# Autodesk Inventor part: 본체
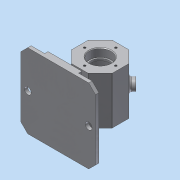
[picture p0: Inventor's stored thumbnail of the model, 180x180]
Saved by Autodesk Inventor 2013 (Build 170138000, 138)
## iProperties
Created: 2018-06
Part Number: 본체
Material: 알루미늄 6061
Document SubType Name: Modeling
Designer: Administrator
Density: 2.71 g/cm^3
Mass: 554.043 g
Surface Area: 601.93 cm^2
Volume: 204.444 cm^3
Author: Administrator
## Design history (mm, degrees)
sketch "스케치2" dims "d0" = 60
  geometry: L1 (12.426, 30)-(30, 12.426); L2 (30, 12.426)-(30, -12.426); L3 (30, -12.426)-(12.426, -30); L4 (12.426, -30)-(-12.426, -30); L5 (-12.426, -30)-(-30, -12.426); L6 (-30, -12.426)-(-30, 12.426); L7 (-30, 12.426)-(-12.426, 30); L8 (-12.426, 30)-(12.426, 30); L9 (-55, -62)-(55, -62); L10 (55, -62)-(55, -57); L11 (55, -57)-(25, -57); L12 (25, -57)-(25, -52); L13 (25, -52)-(-25, -52); L14 (-25, -52)-(-25, -57); L15 (-25, -57)-(-55, -57); L16 (-55, -57)-(-55, -62); L17 (0, 0)-(0, -62); L18 (-5, -30)-(-5, -52); L19 (5, -30)-(5, -52); 3 further points
  constraints: 38 end point, 7 parallel, 4 point on line, 3 perpendicular, 2 coincident, 2 midpoint, 2 vertical alignment, 1 collinear, 1 vertical, 21 other
  dimensions: "d4" = 62 distance of L17.start L17.end; "d5" = 10 distance between parallel lines of L9 L13; "d6" = 5 distance between parallel lines of L9 L15; "d7" = 110 distance of L9.start L9.end; "d8" = 30 distance of L14.end L15.end; "d9" = 10 distance between parallel lines of L18 L19
extrude "돌출1" new body sketch "스케치2" distance "d2" = 35; taper "d3" = 0 deg
extrude "돌출2" join sketch "스케치2" distance "d10" = 55; taper "d11" = 0 deg
extrude "돌출3" join sketch "스케치2" distance "d12" = 24; taper "d13" = 0 deg
chamfer "모따기1" distance "d14" = 10; stored, may be unused: second distance "d15" = 2, angle "d16" = 45 deg
fillet "모깎기1" dims "d17" = 5
hole "구멍1" sketch "스케치2" diameter "d18" = 28; stored, may be unused: countersink angle "d22" = 90 deg, drill point angle "d24" = 118 deg; dims "d19" = 6, "d20" = 50, "d21" = 20, "d23" = 8
hole "구멍2" diameter "d27" = 28; stored, may be unused: countersink angle "d31" = 90 deg, drill point angle "d33" = 118 deg; dims "d25" = 10, "d26" = 10, "d28" = 6, "d29" = 32, "d30" = 12, "d32" = 8
sketch "스케치3"
  geometry: C1 r 8 at (-12.426, 35); 1 further point
  constraints: 1 centre point, 1 coincident
  dimensions: "d35" = 16 diameter of C1
extrude "돌출4" join sketch "스케치3" distance "d36" = 7; taper "d37" = 0 deg
sketch "스케치4"
  geometry: L1 (24.853, 0)-(0, 0) reference; L2 (-17.574, 0)-(-17.574, 70) reference; 2 further points
  constraints: 1 coincident, 1 other
  dimensions: "d78" = 30 distance from line of L2 point (12.426, 35); "d79" = 35 distance from line of L1 point (12.426, 35)
feature "엠보싱1" sketch "스케치4" dims "d0" = 60, "d4" = 62, "d5" = 10, "d6" = 5, "d7" = 110, "d8" = 30, "d9" = 10, "d38" = 0.5, "d39" = 0
hole "구멍3" diameter "d42" = 8; stored, may be unused: countersink angle "d46" = 90 deg, drill point angle "d48" = 118 deg; dims "d40" = 10, "d41" = 10, "d43" = 6, "d44" = 32, "d45" = 12, "d47" = 8
sketch "스케치5"
  geometry: L1 (-10, 100)-(-10, 10) reference; L2 (20, 0)-(0, 0) reference; 2 further points
  dimensions: "d49" = 10 distance from line of L1 point (0, 55); "d50" = 55 distance from line of L2 point (0, 55)
hole "구멍4" sketch "스케치5" at (0, 55) diameter "d51" = 10; stored, may be unused: countersink angle "d55" = 90 deg, drill point angle "d57" = 118 deg; dims "d52" = 6, "d53" = 32, "d54" = 12, "d56" = 8
sketch "스케치6" dims "d58" = 46
  geometry: C1 r 16 at (0, 0) reference; 2 further points
  constraints: 2 vertical alignment, 1 coincident, 2 other
hole "구멍5" sketch "스케치6" at (0, 23) diameter "d60" = 3.242; stored, may be unused: countersink angle "d64" = 90 deg, drill point angle "d66" = 118 deg; dims "d61" = 8, "d62" = 32, "d63" = 12, "d65" = 10
fillet "모깎기2" dims "d70" = 2
fillet "모깎기3" dims "d71" = 0.3
fillet "모깎기4" dims "d72" = 3
fillet "모깎기5" dims "d73" = 1
chamfer "모따기2" distance "d74" = 1; stored, may be unused: second distance "d75" = 2, angle "d76" = 45 deg
node "솔리드1"
mirror "대칭1"
mirror "대칭2"
pattern_circular "원형 패턴1" dims angle "d68" = 360 deg
mirror "대칭3"
